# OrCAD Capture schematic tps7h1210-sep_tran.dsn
size Custom; title: TPS7H1210-SEP 16.5-V, 1-A, Negative Linear Regulator in; rev: *; note: Datasheet: SBVS414    EVM User Guide: SLVUCA1; note: Space Enhanced Plastic
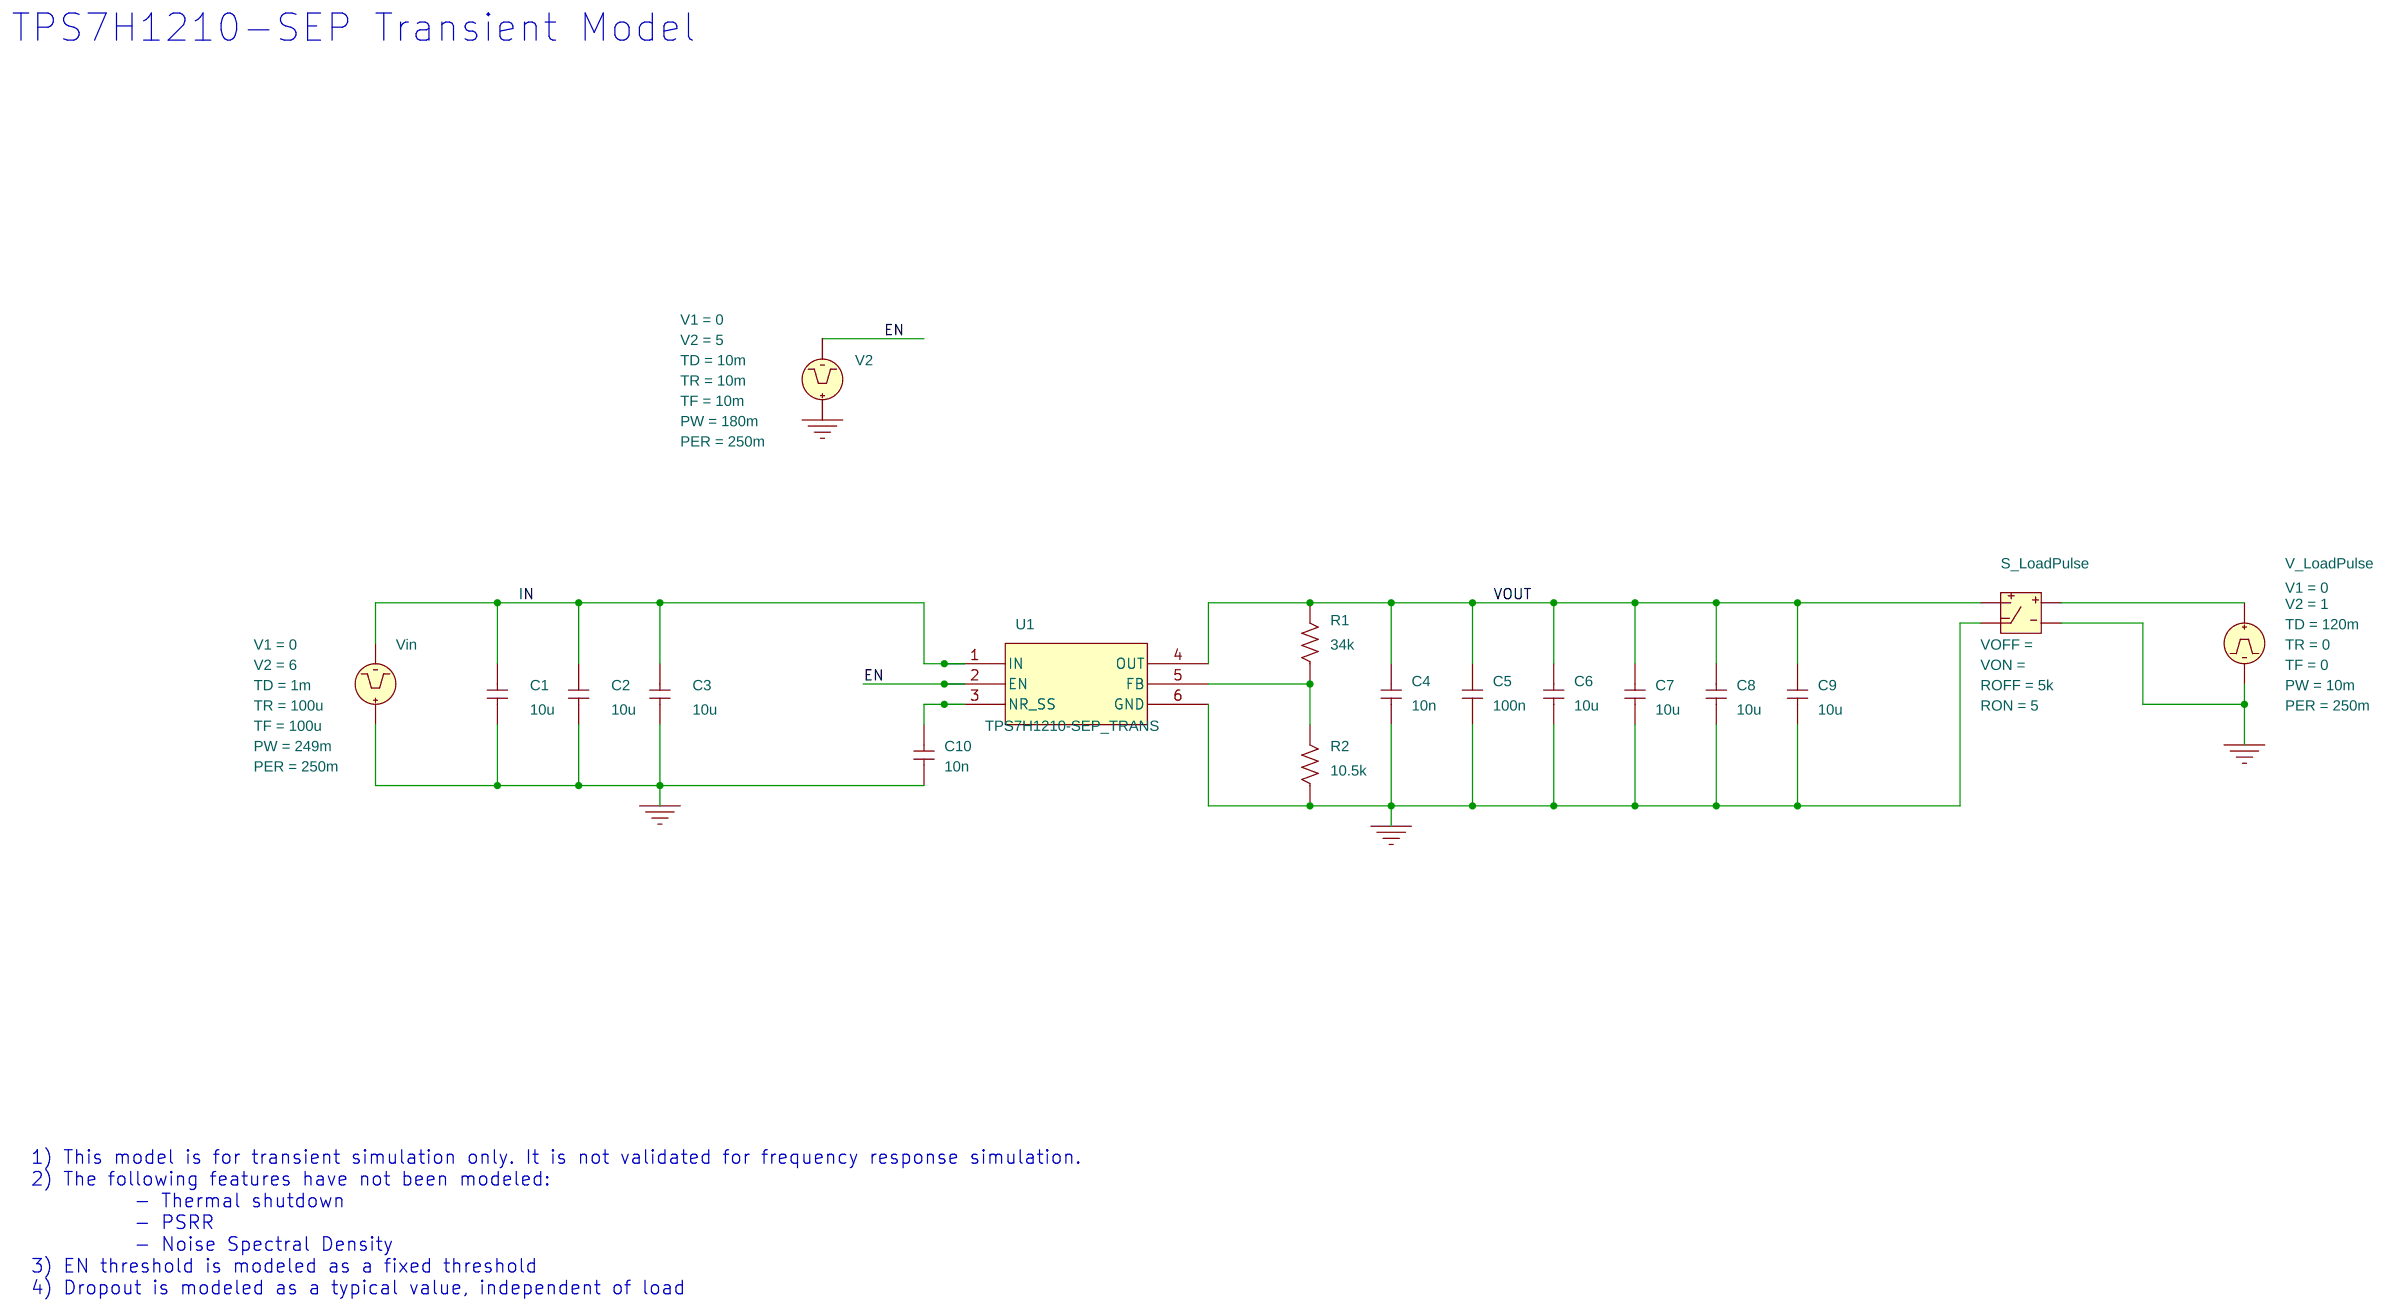
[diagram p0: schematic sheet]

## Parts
C1  10u  [cap196]
C2  10u  [cap196]
C3  10u  [cap196]
C4  10n  [cap196]
C5  100n  [cap196]
C6  10u  [cap196]
C7  10u  [cap196]
C8  10u  [cap196]
C9  10u  [cap196]
C10  10n  [cap196]
R1  34k  [AXRC05]
R2  10.5k  [AXRC05]
S_LoadPulse  S
U1  TPS7H1210-SEP_TRANS
V2  VPULSE
V_LoadPulse  VPULSE
Vin  VPULSE

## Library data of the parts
C1-C10 = C
R1 R2 = R
S_LoadPulse = S: ROFF: 5k; RON: 5
U1 = TPS7H1210-SEP_TRANS_4: PSpiceTemplate: X^@REFDES  %IN %EN %NR_SS %GND %FB %OUT @MODEL
V2 = VPULSE: PER: 250m; PW: 180m; TD: 10m; TF: 10m; TR: 10m; V1: 0; V2: 5
V_LoadPulse = VPULSE: PER: 250m; PW: 10m; TD: 120m; TF: 0; TR: 0; V1: 0; V2: 1
Vin = VPULSE: PER: 250m; PW: 249m; TD: 1m; TF: 100u; TR: 100u; V1: 0; V2: 6

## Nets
0: C1.1 C2.1 C3.1 C4.1 C5.1 C6.1 C7.1 C8.1 C9.1 C10.1 R2.1 S_LoadPulse.1(2) S_LoadPulse.3(4) U1.6(GND) V2.1(+) V_LoadPulse.2(-) Vin.1(+)
EN: U1.2(EN) V2.2(-)
IN: C1.2 C2.2 C3.2 U1.1(IN) Vin.2(-)
VOUT: C4.2 C5.2 C6.2 C7.2 C8.2 C9.2 R1.2 S_LoadPulse.2(3) U1.4(OUT)
N30251: R1.1 R2.2 U1.5(FB)
N30381: C10.2 U1.3(NR_SS)
N16777487: S_LoadPulse.0(1) V_LoadPulse.1(+)

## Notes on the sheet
- TPS7H1210-SEP Transient Model
- 1) This model is for transient simulation only. It is not validated for frequency response simulation.
  2) The following features have not been modeled:
            - Thermal shutdown
            - PSRR
            - Noise Spectral Density
  3) EN threshold is modeled as a fixed threshold
  4) Dropout is modeled as a typical value, independent of load
